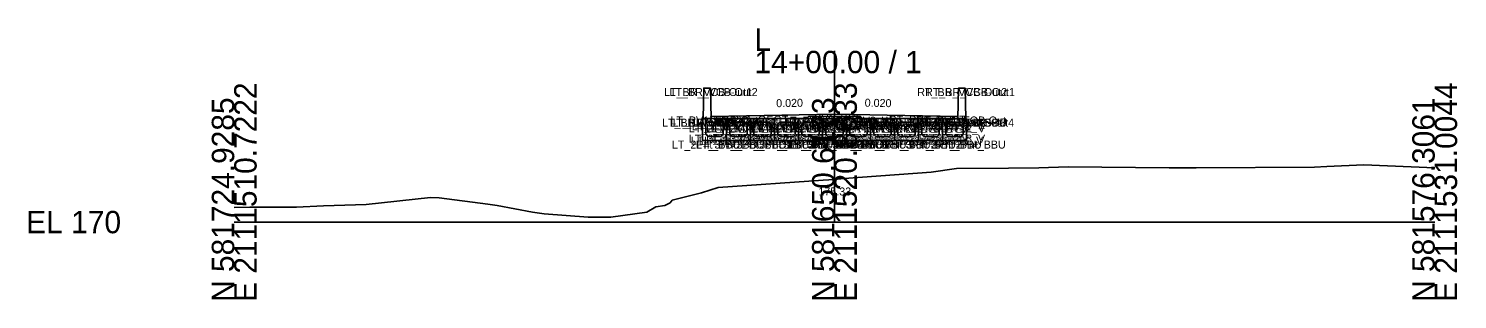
# Model space of a CAD drawing. Extents: x -26 to 3453, y -333 to 9539.
# Drawn here: x -25.7 to 152.8, y 3990.3 to 4024.2 of the extents above; entities that cross this region are included whole.
import ezdxf

# ---------------------------------------------------------------- set-up
doc = ezdxf.new("R2010")
doc.units = 0
for name, color, linetype in [('Default', 7, 'Continuous'), ('Exist Cross Section Cell', 7, 'Continuous'), ('Exist XS Center Line Elevation Label', 7, 'Continuous'), ('Exist XS Ground Line', 7, 'Continuous'), ('Prop CMT Concrete Structures', 7, 'Continuous'), ('Prop CMT Pvmt Course 1', 7, 'Continuous'), ('Prop XS SE Text', 7, 'Continuous'), ('Scratch_Level_0', 7, 'Continuous')]:
    doc.layers.add(name, color=color, linetype=linetype)

msp = doc.modelspace()

# ---------------------------------------------------------------- linework, layer by layer
at = {"layer": 'Exist Cross Section Cell'}
for p, q in [((75, 4000), (75, 4021.44)), ((0, 4000), (75, 4000)), ((75, 4000), (150, 4000))]:
    msp.add_line(p, q, dxfattribs=at)
at = {"layer": 'Exist XS Ground Line'}
for p, q in [((87.1, 4006.26), (90.25, 4006.72)), ((90.25, 4006.72), (96.75, 4006.77)), ((96.75, 4006.77), (100.54, 4006.78)), ((100.54, 4006.78), (104.21, 4006.93)), ((104.21, 4006.93), (116.83, 4006.8)), ((116.83, 4006.8), (120.2, 4006.8)), ((120.2, 4006.8), (134.97, 4006.88)), ((134.97, 4006.88), (136.51, 4006.94)), ((136.51, 4006.94), (141.16, 4007.15)), ((141.16, 4007.15), (150, 4006.81)), ((60.48, 4004.33), (73.61, 4005.25)), ((73.61, 4005.25), (75, 4005.33)), ((75, 4005.33), (75.81, 4005.41)), ((75.81, 4005.41), (76.23, 4005.47)), ((76.23, 4005.47), (87.1, 4006.26)), ((16.48, 4002.18), (24.51, 4003.06)), ((24.51, 4003.06), (25.63, 4003.02)), ((25.63, 4003.02), (31.67, 4002.23)), ((54.48, 4002.42), (54.72, 4002.73)), ((54.72, 4002.73), (56.55, 4003.19)), ((56.55, 4003.19), (58.37, 4003.66)), ((58.37, 4003.66), (60.48, 4004.33)), ((0, 4001.84), (1.97, 4001.85)), ((1.97, 4001.85), (7.77, 4001.85)), ((7.77, 4001.85), (11.16, 4002.02)), ((11.16, 4002.02), (16.48, 4002.18)), ((31.67, 4002.23), (32.85, 4002.07)), ((32.85, 4002.07), (37.29, 4001.24)), ((37.29, 4001.24), (38.72, 4001.04)), ((38.72, 4001.04), (44.22, 4000.61)), ((47.04, 4000.63), (51.57, 4001.23)), ((51.57, 4001.23), (52.7, 4001.89)), ((52.7, 4001.89), (53.8, 4002.09)), ((53.8, 4002.09), (54.48, 4002.42)), ((44.22, 4000.61), (47.04, 4000.63))]:
    msp.add_line(p, q, dxfattribs=at)
at = {"layer": 'Prop CMT Concrete Structures'}
for points in [[(59.58, 4012.95), (59.5, 4016.78), (58.66, 4016.78), (58.58, 4012.95)], [(90.42, 4012.95), (90.5, 4016.78), (91.33, 4016.78), (91.42, 4012.95)], [(61.5, 4012.95), (58.5, 4012.95)], [(58.5, 4012.95), (58.5, 4010.2)], [(58.58, 4012.95), (59.58, 4012.95)], [(58.92, 4012.24), (59.17, 4012.49)], [(58.92, 4010.95), (58.92, 4012.24)], [(59.17, 4012.49), (60.83, 4012.49), (61.08, 4012.24)], [(61.08, 4012.24), (61.08, 4010.95)], [(64.5, 4012.95), (61.5, 4012.95)], [(61.5, 4012.95), (61.5, 4010.2)], [(61.5, 4010.2), (61.5, 4012.95)], [(61.92, 4012.24), (62.17, 4012.49)], [(61.92, 4010.95), (61.92, 4012.24)], [(62.17, 4012.49), (63.83, 4012.49), (64.08, 4012.24)], [(64.08, 4012.24), (64.08, 4010.95)], [(67.5, 4012.95), (64.5, 4012.95)], [(64.5, 4012.95), (64.5, 4010.2)], [(64.5, 4010.2), (64.5, 4012.95)], [(64.92, 4012.24), (65.17, 4012.49)], [(64.92, 4010.95), (64.92, 4012.24)], [(65.17, 4012.49), (66.83, 4012.49), (67.08, 4012.24)], [(67.08, 4012.24), (67.08, 4010.95)], [(70.5, 4012.95), (67.5, 4012.95)], [(67.5, 4012.95), (67.5, 4010.2)], [(67.5, 4010.2), (67.5, 4012.95)], [(67.92, 4012.24), (68.17, 4012.49)], [(67.92, 4010.95), (67.92, 4012.24)], [(68.17, 4012.49), (69.83, 4012.49), (70.08, 4012.24)], [(70.08, 4012.24), (70.08, 4010.95)], [(70.5, 4010.2), (70.5, 4012.95)], [(73.51, 4012.95), (70.5, 4012.95)], [(70.5, 4012.95), (70.5, 4010.2)], [(70.92, 4012.24), (71.17, 4012.49)], [(70.92, 4010.95), (70.92, 4012.24)], [(71.17, 4012.49), (72.84, 4012.49), (73.09, 4012.24)], [(73.09, 4012.24), (73.09, 4010.95)], [(75, 4012.95), (73.51, 4012.95)], [(73.51, 4012.95), (73.51, 4010.2)], [(73.51, 4010.2), (73.51, 4012.95)], [(73.93, 4012.24), (74.18, 4012.49), (75, 4012.49)], [(73.93, 4010.95), (73.93, 4012.24)], [(75, 4012.95), (76.49, 4012.95)], [(76.07, 4012.24), (75.82, 4012.49), (75, 4012.49)], [(76.07, 4010.95), (76.07, 4012.24)], [(76.49, 4012.95), (76.49, 4010.2)], [(76.5, 4012.95), (79.5, 4012.95)], [(76.5, 4010.2), (76.5, 4012.95)], [(78.83, 4012.49), (77.17, 4012.49), (76.92, 4012.24)], [(76.92, 4012.24), (76.92, 4010.95)], [(79.08, 4012.24), (78.83, 4012.49)], [(79.08, 4010.95), (79.08, 4012.24)], [(79.5, 4012.95), (82.5, 4012.95)], [(79.5, 4010.2), (79.5, 4012.95)], [(79.5, 4012.95), (79.5, 4010.2)], [(81.83, 4012.49), (80.17, 4012.49), (79.92, 4012.24)], [(79.92, 4012.24), (79.92, 4010.95)], [(82.08, 4012.24), (81.83, 4012.49)], [(82.08, 4010.95), (82.08, 4012.24)], [(82.5, 4012.95), (82.5, 4010.2)], [(82.5, 4012.95), (85.5, 4012.95)], [(82.5, 4010.2), (82.5, 4012.95)], [(84.83, 4012.49), (83.17, 4012.49), (82.92, 4012.24)], [(82.92, 4012.24), (82.92, 4010.95)], [(85.08, 4012.24), (84.83, 4012.49)], [(85.08, 4010.95), (85.08, 4012.24)], [(85.5, 4012.95), (85.5, 4010.2)], [(85.5, 4012.95), (88.5, 4012.95)], [(85.5, 4010.2), (85.5, 4012.95)], [(87.83, 4012.49), (86.17, 4012.49), (85.92, 4012.24)], [(85.92, 4012.24), (85.92, 4010.95)], [(88.08, 4012.24), (87.83, 4012.49)], [(88.08, 4010.95), (88.08, 4012.24)], [(88.5, 4012.95), (88.5, 4010.2)], [(88.5, 4012.95), (91.5, 4012.95)], [(88.5, 4010.2), (88.5, 4012.95)], [(90.83, 4012.49), (89.17, 4012.49), (88.92, 4012.24)], [(88.92, 4012.24), (88.92, 4010.95)], [(91.42, 4012.95), (90.42, 4012.95)], [(91.08, 4012.24), (90.83, 4012.49)], [(91.08, 4010.95), (91.08, 4012.24)], [(91.5, 4012.95), (91.5, 4010.2)], [(58.5, 4010.2), (61.5, 4010.2)], [(61.08, 4010.95), (60.83, 4010.7), (59.17, 4010.7), (58.92, 4010.95)], [(61.5, 4010.2), (64.5, 4010.2)], [(64.08, 4010.95), (63.83, 4010.7), (62.17, 4010.7), (61.92, 4010.95)], [(64.5, 4010.2), (67.5, 4010.2)], [(67.08, 4010.95), (66.83, 4010.7), (65.17, 4010.7), (64.92, 4010.95)], [(67.5, 4010.2), (70.5, 4010.2)], [(70.08, 4010.95), (69.83, 4010.7), (68.17, 4010.7), (67.92, 4010.95)], [(70.5, 4010.2), (73.51, 4010.2)], [(73.09, 4010.95), (72.84, 4010.7), (71.17, 4010.7), (70.92, 4010.95)], [(73.51, 4010.2), (75, 4010.2)], [(75, 4010.7), (74.18, 4010.7), (73.93, 4010.95)], [(75, 4010.7), (75.82, 4010.7), (76.07, 4010.95)], [(76.49, 4010.2), (75, 4010.2)], [(79.5, 4010.2), (76.5, 4010.2)], [(76.92, 4010.95), (77.17, 4010.7), (78.83, 4010.7), (79.08, 4010.95)], [(82.5, 4010.2), (79.5, 4010.2)], [(79.92, 4010.95), (80.17, 4010.7), (81.83, 4010.7), (82.08, 4010.95)], [(85.5, 4010.2), (82.5, 4010.2)], [(82.92, 4010.95), (83.17, 4010.7), (84.83, 4010.7), (85.08, 4010.95)], [(88.5, 4010.2), (85.5, 4010.2)], [(85.92, 4010.95), (86.17, 4010.7), (87.83, 4010.7), (88.08, 4010.95)], [(91.5, 4010.2), (88.5, 4010.2)], [(88.92, 4010.95), (89.17, 4010.7), (90.83, 4010.7), (91.08, 4010.95)]]:
    msp.add_lwpolyline(points, dxfattribs=at)
at = {"layer": 'Prop CMT Pvmt Course 1'}
for points in [[(75, 4013.53), (64, 4013.31), (59.57, 4013.22)], [(75, 4013.28), (75, 4013.53)], [(75, 4013.53), (86, 4013.31), (90.42, 4013.22)], [(75, 4013.28), (75, 4013.53)], [(59.57, 4013.22), (59.58, 4012.95), (61.34, 4012.95), (71.5, 4012.95), (71.76, 4013.2), (75, 4013.28)], [(90.42, 4013.22), (90.42, 4012.95), (88.66, 4012.95), (78.5, 4012.95), (78.24, 4013.2), (75, 4013.28)]]:
    msp.add_lwpolyline(points, dxfattribs=at)

# ---------------------------------------------------------------- texts
at = {"layer": 'Default'}
msp.add_text('-', height=0.0001, dxfattribs=at).set_placement((0, 4000))
at = {"layer": 'Exist Cross Section Cell'}
for s, p in [('L', (65, 4021.44)), ('14+00.00 / 1', (65, 4018.64)), ('EL 170', (-26, 3998.6))]:
    msp.add_text(s, height=2.8, dxfattribs=at).set_placement(p)
for s, p in [('E 2111510.7222', (2.8, 3990)), ('E 2111520.8633', (77.8, 3990)), ('E 2111531.0044', (152.8, 3990)), ('N 581724.9285', (0, 3990)), ('N 581650.6173', (75, 3990)), ('N 581576.3061', (150, 3990))]:
    msp.add_text(s, height=2.8, rotation=90, dxfattribs=at).set_placement(p)
at = {"layer": 'Exist XS Center Line Elevation Label'}
msp.add_text('175.33', height=1, dxfattribs=at).set_placement((73, 4003.33))
at = {"layer": 'Prop XS SE Text'}
for rotation, p in [(1.1458, (67.73, 4014.38)), (358.8542, (78.77, 4014.45))]:
    msp.add_text('0.020', height=1, rotation=rotation, dxfattribs=at).set_placement(p)
at = {"layer": 'Scratch_Level_0'}
for s, p in [('LT_BR_VCB-Out1', (53.71, 4015.78)), ('LT_BR_VCB-Out2', (54.4, 4015.78)), ('RT_BR_VCB-Out2', (85.35, 4015.78)), ('RT_BR_VCB-Out1', (86.32, 4015.78)), ('PV1_PGL', (72.47, 4012.53)), ('LT_BR_VCB-Out4', (53.45, 4011.95)), ('LT_BR_VCB-Out3', (54.47, 4011.95)), ('LT_PV1_FOB-Out', (54.5, 4012.22)), ('LT_1Pnt_BBU', (54.81, 4011.95)), ('LT_2_V', (56.81, 4011.24)), ('LT_1_V', (57.18, 4011.49)), ('LT_4Pnt_BBU', (57.69, 4011.95)), ('LT_PV1_Tent', (57.75, 4011.95)), ('LT_8_V', (58.73, 4011.49)), ('LT_7_V', (58.98, 4011.24)), ('LT_2_V1', (59.64, 4011.24)), ('LT_PV1_OEOT', (59.87, 4012.31)), ('LT_1_V1', (60.01, 4011.49)), ('LT_4Pnt_BBU1', (60.45, 4011.95)), ('LT_8_V1', (61.56, 4011.49)), ('LT_7_V1', (61.81, 4011.24)), ('LT_2_V2', (62.49, 4011.24)), ('LT_1_V2', (62.86, 4011.49)), ('LT_4Pnt_BBU2', (63.31, 4011.95)), ('LT_8_V2', (64.41, 4011.49)), ('LT_7_V2', (64.66, 4011.24)), ('LT_2_V3', (65.48, 4011.24)), ('LT_1_V3', (65.85, 4011.49)), ('LT_4Pnt_BBU3', (66.29, 4011.95)), ('LT_8_V3', (67.39, 4011.49)), ('LT_7_V3', (67.64, 4011.24)), ('LT_2_V6', (68.47, 4011.24)), ('LT_PV2_W', (68.7, 4012.2)), ('LT_1_V6', (68.83, 4011.49)), ('LT_BR_W', (68.85, 4011.95)), ('LT_4Pnt_BBU5', (69.3, 4011.95)), ('LT_1Pnt_BBU1', (69.58, 4011.95)), ('LT_8_V5', (70.4, 4011.49)), ('LT_7_V5', (70.65, 4011.24)), ('LT_2_V4', (71.47, 4011.24)), ('LT_1_V4', (71.84, 4011.49)), ('RT_4Pnt_BBU5', (72.23, 4011.95)), ('PV2_PGL', (72.35, 4012.28)), ('RT_1Pnt_BBU1', (72.5, 4011.95)), ('BR_PGL', (72.75, 4011.95)), ('RT_1_V4', (73.43, 4011.49)), ('6_V4', (73.51, 4011.49)), ('RT_2_V4', (73.56, 4011.24)), ('RT_7_V5', (74.41, 4011.24)), ('RT_8_V5', (74.66, 4011.49)), ('RT_PV2_W', (75.12, 4012.2)), ('RT_4Pnt_BBU3', (75.23, 4011.95)), ('RT_BR_W', (75.78, 4011.95)), ('RT_1_V6', (76.44, 4011.49)), ('RT_2_V6', (76.57, 4011.24)), ('RT_7_V3', (77.42, 4011.24)), ('RT_8_V3', (77.67, 4011.49)), ('RT_4Pnt_BBU2', (78.25, 4011.95)), ('RT_1_V3', (79.45, 4011.49)), ('RT_2_V3', (79.59, 4011.24)), ('RT_7_V2', (80.43, 4011.24)), ('RT_8_V2', (80.68, 4011.49)), ('RT_4Pnt_BBU1', (81.39, 4011.95)), ('RT_PV1_OEOT', (81.81, 4012.31)), ('RT_1_V2', (82.47, 4011.49)), ('RT_2_V2', (82.6, 4011.24)), ('RT_7_V1', (83.58, 4011.24)), ('RT_8_V1', (83.83, 4011.49)), ('RT_4Pnt_BBU', (84.63, 4011.95)), ('RT_PV1_Tent', (85.01, 4011.95)), ('RT_BR_VCB-Out3', (85.25, 4011.95)), ('RT_PV1_FOB-Out', (85.29, 4012.22)), ('RT_1_V1', (85.62, 4011.49)), ('RT_2_V1', (85.75, 4011.24)), ('RT_BR_VCB-Out4', (86.23, 4011.95)), ('RT_7_V', (86.76, 4011.24)), ('RT_8_V', (87.01, 4011.49)), ('RT_1Pnt_BBU', (87.75, 4011.95)), ('RT_1_V', (88.79, 4011.49)), ('RT_2_V', (88.92, 4011.24)), ('LT_2Pnt_BBU', (54.69, 4009.2)), ('LT_3_V', (56.81, 4009.95)), ('LT_4_V', (57.06, 4009.7)), ('LT_3Pnt_BBU', (57.69, 4009.2)), ('LT_5_V', (58.73, 4009.7)), ('LT_6_V', (58.98, 4009.95)), ('LT_3_V1', (59.64, 4009.95)), ('LT_4_V1', (59.89, 4009.7)), ('LT_3Pnt_BBU1', (60.45, 4009.2)), ('LT_5_V1', (61.56, 4009.7)), ('LT_6_V1', (61.81, 4009.95)), ('LT_3_V2', (62.49, 4009.95)), ('LT_4_V2', (62.74, 4009.7)), ('LT_3Pnt_BBU2', (63.31, 4009.2)), ('LT_5_V2', (64.41, 4009.7)), ('LT_6_V2', (64.66, 4009.95)), ('LT_3_V3', (65.48, 4009.95)), ('LT_4_V3', (65.73, 4009.7)), ('LT_3Pnt_BBU3', (66.29, 4009.2)), ('LT_5_V3', (67.39, 4009.7)), ('LT_6_V3', (67.64, 4009.95)), ('LT_3_V6', (68.47, 4009.95)), ('LT_4_V6', (68.72, 4009.7)), ('LT_3Pnt_BBU6', (69.29, 4009.2)), ('LT_2Pnt_BBU1', (69.46, 4009.2)), ('LT_5_V6', (70.39, 4009.7)), ('LT_6_V6', (70.64, 4009.95)), ('LT_3_V4', (71.47, 4009.95)), ('3Pnt_BBU4', (71.74, 4009.2)), ('LT_4_V4', (71.72, 4009.7)), ('RT_3Pnt_BBU6', (72.22, 4009.2)), ('RT_2Pnt_BBU1', (72.38, 4009.2)), ('RT_4_V4', (73.31, 4009.7)), ('5_V4', (73.51, 4009.7)), ('RT_3_V4', (73.56, 4009.95)), ('RT_6_V6', (74.41, 4009.95)), ('RT_5_V6', (74.66, 4009.7)), ('RT_3Pnt_BBU3', (75.23, 4009.2)), ('RT_4_V6', (76.32, 4009.7)), ('RT_3_V6', (76.57, 4009.95)), ('RT_6_V3', (77.42, 4009.95)), ('RT_5_V3', (77.67, 4009.7)), ('RT_3Pnt_BBU2', (78.25, 4009.2)), ('RT_4_V3', (79.34, 4009.7)), ('RT_3_V3', (79.59, 4009.95)), ('RT_6_V2', (80.43, 4009.95)), ('RT_5_V2', (80.68, 4009.7)), ('RT_3Pnt_BBU1', (81.39, 4009.2)), ('RT_4_V2', (82.35, 4009.7)), ('RT_3_V2', (82.6, 4009.95)), ('RT_6_V1', (83.58, 4009.95)), ('RT_5_V1', (83.83, 4009.7)), ('RT_3Pnt_BBU', (84.63, 4009.2)), ('RT_4_V1', (85.5, 4009.7)), ('RT_3_V1', (85.75, 4009.95)), ('RT_6_V', (86.76, 4009.95)), ('RT_5_V', (87.01, 4009.7)), ('RT_2Pnt_BBU', (87.63, 4009.2)), ('RT_4_V', (88.67, 4009.7)), ('RT_3_V', (88.92, 4009.95))]:
    msp.add_text(s, height=1, dxfattribs=at).set_placement(p)

doc.saveas('drawing.dxf')
